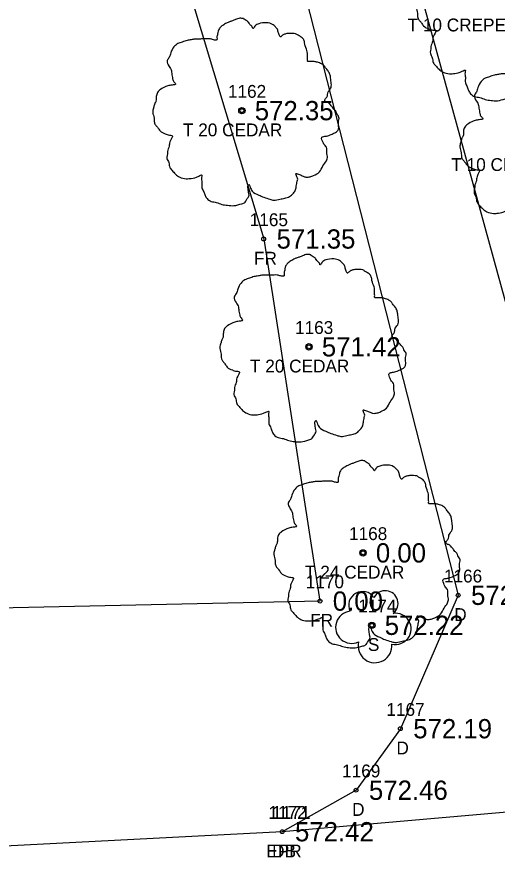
# Model space of a CAD drawing. Extents: x 1529475 to 1532053, y 876698 to 877911.
# Drawn here: x 1531018 to 1531055.4, y 877286.3 to 877352.1 of the extents above; entities that cross this region are included whole.
import ezdxf

# ---------------------------------------------------------------- set-up
doc = ezdxf.new("R2010")
doc.units = 0
for name, color, linetype in [('RD_EX_Driveway', 7, 'Continuous'), ('RD_EX_Driveway_txCode', 7, 'Continuous'), ('RD_EX_Fence_Other', 7, 'Continuous'), ('RD_EX_Fence_Other_txCode', 7, 'Continuous'), ('RD_EX_Road', 7, 'Continuous'), ('RD_EX_Road_txCode', 7, 'Continuous'), ('RD_EX_TX_Driveway_ELEV', 7, 'Continuous'), ('RD_EX_TX_Fence_Other_ELEV', 7, 'Continuous'), ('RD_EX_TX_Road_ELEV', 7, 'Continuous'), ('RD_EX_TX_VEG_ELEV', 7, 'Continuous'), ('RD_EX_VEG', 7, 'Continuous'), ('RD_EX_VEG_txCode', 7, 'Continuous'), ('RD_SMD_Locator', 7, 'Continuous')]:
    doc.layers.add(name, color=color, linetype=linetype)

msp = doc.modelspace()

# ---------------------------------------------------------------- linework, layer by layer
at = {"layer": 'RD_EX_Driveway'}
for points in [[(1531081.114, 877292.384), (1531071.715, 877299.875), (1531056.729, 877327.604), (1531041.174, 877384.235)], [(1531033.235, 877382.278), (1531052.392, 877307.085), (1531047.892, 877296.694), (1531044.444, 877291.901), (1531038.69, 877288.667)]]:
    msp.add_lwpolyline(points, dxfattribs=at)
at = {"layer": 'RD_EX_Fence_Other'}
msp.add_lwpolyline([(1531024.548, 877377.186), (1531037.254, 877334.843), (1531041.631, 877306.635), (1530974.749, 877305.169), (1530894.744, 877304.424), (1530859.113, 877317.256)], dxfattribs=at)
at = {"layer": 'RD_EX_Road'}
msp.add_lwpolyline([(1531606.641, 877133.837), (1531579.15, 877155.048), (1531564.866, 877165.268), (1531535.216, 877186.029), (1531511.532, 877200.27), (1531474.57, 877218.901), (1531430.451, 877239.347), (1531404.48, 877249.379), (1531382.323, 877256.431), (1531333.233, 877270.709), (1531303.666, 877277.444), (1531276.518, 877282.709), (1531237.324, 877287.202), (1531185.802, 877290.94), (1531132.609, 877292.767), (1531081.114, 877292.384), (1531038.69, 877288.667), (1530976.423, 877285.451), (1530941.057, 877284.256)], dxfattribs=at)
at = {"layer": 'RD_EX_VEG'}
for centre, radius in [((1531035.56, 877344.843), 0.25), ((1531035.548, 877344.824), 0.0001), ((1531040.78, 877326.444), 0.25), ((1531040.767, 877326.425), 0.0001), ((1531044.983, 877310.389), 0.25), ((1531044.97, 877310.37), 0.0001), ((1531045.671, 877304.748), 0.25)]:
    msp.add_circle(centre, radius, dxfattribs=at)
for centre, radius, start, end in [((1531044.95, 877306.295), 1.084, 34.97629, 204.75602), ((1531046.716, 877306.45), 0.995, 308.76261, 152.04674), ((1531044.107, 877304.592), 1.257, 96.45179, 294.73401), ((1531047.511, 877304.469), 1.218, 256.56668, 98.10463), ((1531045.917, 877303.152), 1.318, 166.88266, 5.75893)]:
    msp.add_arc(centre, radius, start, end, dxfattribs=at)
for points in [[(1531056.197, 877360.182), (1531055.897, 877360.207), (1531055.572, 877360.107), (1531055.322, 877360.007), (1531055.097, 877359.932), (1531054.872, 877359.832), (1531054.572, 877359.658), (1531054.347, 877359.458), (1531054.222, 877359.208), (1531054.172, 877358.983), (1531054.123, 877358.708), (1531054.123, 877358.533), (1531053.998, 877358.508), (1531053.848, 877358.533), (1531053.598, 877358.608), (1531053.348, 877358.608), (1531053.098, 877358.608), (1531052.748, 877358.583), (1531052.398, 877358.583), (1531052.123, 877358.533), (1531051.799, 877358.483), (1531051.424, 877358.358), (1531051.074, 877358.233), (1531050.774, 877357.983), (1531050.524, 877357.509), (1531050.399, 877357.159), (1531050.249, 877356.909), (1531050.399, 877356.459), (1531050.574, 877356.109), (1531050.599, 877355.909), (1531050.674, 877355.484), (1531050.774, 877355.26), (1531050.899, 877355.06), (1531050.824, 877355.035), (1531050.449, 877354.985), (1531050.149, 877354.885), (1531049.724, 877354.66), (1531049.5, 877354.435), (1531049.4, 877354.11), (1531049.375, 877353.76), (1531049.275, 877353.56), (1531049.2, 877353.285), (1531049.175, 877353.21), (1531049.125, 877352.886), (1531049.225, 877352.436), (1531049.25, 877352.086), (1531049.375, 877351.861), (1531049.525, 877351.686), (1531049.699, 877351.436), (1531050.099, 877351.211), (1531050.424, 877351.111), (1531050.624, 877351.086), (1531050.449, 877350.587), (1531050.399, 877350.237), (1531050.274, 877349.837), (1531050.274, 877349.762), (1531050.224, 877349.287), (1531050.374, 877348.962), (1531050.449, 877348.587), (1531050.624, 877348.363), (1531050.899, 877348.063), (1531051.224, 877347.838), (1531051.724, 877347.713), (1531052.123, 877347.738), (1531052.698, 877347.913), (1531052.948, 877347.988), (1531052.923, 877347.813), (1531052.948, 877347.438), (1531052.948, 877347.013), (1531053.098, 877346.688), (1531053.198, 877346.413), (1531053.348, 877346.163), (1531053.673, 877345.939), (1531054.073, 877345.864), (1531054.497, 877345.714), (1531054.947, 877345.639), (1531055.447, 877345.614), (1531056.047, 877345.764), (1531056.322, 877345.889), (1531056.422, 877346.064), (1531056.621, 877346.438), (1531056.571, 877346.663), (1531056.596, 877347.263), (1531056.696, 877347.088), (1531056.871, 877346.738), (1531057.371, 877346.438), (1531057.771, 877346.263), (1531058.246, 877346.113), (1531058.546, 877346.039), (1531059.02, 877346.113), (1531059.395, 877346.188), (1531059.77, 877346.313), (1531060.07, 877346.588), (1531060.245, 877346.863), (1531060.295, 877347.138), (1531060.37, 877347.513), (1531060.42, 877347.688)], [(1531035.692, 877352.01), (1531035.392, 877352.035), (1531035.067, 877351.935), (1531034.817, 877351.835), (1531034.593, 877351.76), (1531034.368, 877351.66), (1531034.068, 877351.486), (1531033.843, 877351.286), (1531033.718, 877351.036), (1531033.668, 877350.811), (1531033.618, 877350.536), (1531033.618, 877350.361), (1531033.493, 877350.336), (1531033.343, 877350.361), (1531033.093, 877350.436), (1531032.843, 877350.436), (1531032.593, 877350.436), (1531032.244, 877350.411), (1531031.894, 877350.411), (1531031.619, 877350.361), (1531031.294, 877350.311), (1531030.919, 877350.186), (1531030.569, 877350.061), (1531030.269, 877349.811), (1531030.02, 877349.336), (1531029.895, 877348.987), (1531029.745, 877348.737), (1531029.895, 877348.287), (1531030.07, 877347.937), (1531030.094, 877347.737), (1531030.169, 877347.312), (1531030.269, 877347.087), (1531030.394, 877346.887), (1531030.319, 877346.863), (1531029.945, 877346.813), (1531029.645, 877346.713), (1531029.22, 877346.488), (1531028.995, 877346.263), (1531028.895, 877345.938), (1531028.87, 877345.588), (1531028.77, 877345.388), (1531028.695, 877345.113), (1531028.67, 877345.038), (1531028.62, 877344.713), (1531028.72, 877344.264), (1531028.745, 877343.914), (1531028.87, 877343.689), (1531029.02, 877343.514), (1531029.195, 877343.264), (1531029.595, 877343.039), (1531029.92, 877342.939), (1531030.119, 877342.914), (1531029.945, 877342.414), (1531029.895, 877342.065), (1531029.77, 877341.665), (1531029.77, 877341.59), (1531029.72, 877341.115), (1531029.87, 877340.79), (1531029.945, 877340.415), (1531030.119, 877340.19), (1531030.394, 877339.891), (1531030.719, 877339.666), (1531031.219, 877339.541), (1531031.619, 877339.566), (1531032.194, 877339.741), (1531032.443, 877339.816), (1531032.418, 877339.641), (1531032.443, 877339.266), (1531032.443, 877338.841), (1531032.593, 877338.516), (1531032.693, 877338.241), (1531032.843, 877337.991), (1531033.168, 877337.767), (1531033.568, 877337.692), (1531033.993, 877337.542), (1531034.443, 877337.467), (1531034.942, 877337.442), (1531035.542, 877337.592), (1531035.817, 877337.717), (1531035.917, 877337.891), (1531036.117, 877338.266), (1531036.067, 877338.491), (1531036.092, 877339.091), (1531036.192, 877338.916), (1531036.367, 877338.566), (1531036.867, 877338.266), (1531037.266, 877338.091), (1531037.741, 877337.941), (1531038.041, 877337.866), (1531038.516, 877337.941), (1531038.891, 877338.016), (1531039.265, 877338.141), (1531039.565, 877338.416), (1531039.74, 877338.691), (1531039.79, 877338.966), (1531039.865, 877339.341), (1531039.915, 877339.516)], [(1531039.915, 877339.516), (1531039.84, 877339.691), (1531039.79, 877339.941), (1531039.865, 877339.916), (1531040.04, 877339.866), (1531040.315, 877339.741), (1531040.54, 877339.666), (1531040.865, 877339.691), (1531041.14, 877339.791), (1531041.589, 877340.066), (1531041.864, 877340.54), (1531042.139, 877340.94), (1531042.214, 877341.265), (1531042.164, 877341.49), (1531042.139, 877341.99), (1531041.939, 877342.24), (1531041.889, 877342.364), (1531041.789, 877342.764), (1531041.864, 877342.814), (1531042.139, 877342.864), (1531042.514, 877342.989), (1531042.789, 877343.114), (1531043.014, 877343.289), (1531043.089, 877343.514), (1531043.064, 877343.914), (1531043.114, 877344.314), (1531043.039, 877344.464), (1531042.939, 877344.613), (1531042.864, 877344.813), (1531042.714, 877344.963), (1531042.614, 877345.113), (1531042.514, 877345.213), (1531042.389, 877345.363), (1531042.214, 877345.488), (1531042.064, 877345.538), (1531042.014, 877345.688), (1531042.164, 877345.888), (1531042.214, 877345.988), (1531042.239, 877346.213), (1531042.464, 877346.563), (1531042.514, 877346.962), (1531042.464, 877347.387), (1531042.414, 877347.662), (1531042.264, 877347.937), (1531042.064, 877348.187), (1531041.939, 877348.362), (1531041.764, 877348.487), (1531041.44, 877348.612), (1531041.19, 877348.662), (1531040.84, 877348.662), (1531040.64, 877348.712), (1531040.665, 877348.762), (1531040.665, 877348.912), (1531040.665, 877349.187), (1531040.59, 877349.636), (1531040.44, 877350.136), (1531040.44, 877350.161), (1531040.34, 877350.411), (1531040.115, 877350.611), (1531039.94, 877350.711), (1531039.74, 877350.836), (1531039.49, 877350.861), (1531039.191, 877350.861), (1531038.916, 877350.811), (1531038.716, 877350.711), (1531038.541, 877350.586), (1531038.466, 877350.736), (1531038.366, 877351.036), (1531038.316, 877351.186), (1531038.166, 877351.361), (1531037.941, 877351.56), (1531037.491, 877351.685), (1531036.867, 877351.61), (1531036.567, 877351.411), (1531036.417, 877351.236), (1531036.367, 877351.361), (1531036.167, 877351.56), (1531036.067, 877351.735), (1531035.892, 877351.86), (1531035.742, 877351.96), (1531035.642, 877352.01)], [(1531059.602, 877349.308), (1531059.302, 877349.333), (1531058.977, 877349.233), (1531058.728, 877349.133), (1531058.503, 877349.058), (1531058.278, 877348.958), (1531057.978, 877348.783), (1531057.753, 877348.583), (1531057.628, 877348.333), (1531057.578, 877348.108), (1531057.528, 877347.834), (1531057.528, 877347.659), (1531057.403, 877347.634), (1531057.253, 877347.659), (1531057.003, 877347.734), (1531056.753, 877347.734), (1531056.503, 877347.734), (1531056.154, 877347.709), (1531055.804, 877347.709), (1531055.529, 877347.659), (1531055.204, 877347.609), (1531054.829, 877347.484), (1531054.479, 877347.359), (1531054.18, 877347.109), (1531053.93, 877346.634), (1531053.805, 877346.284), (1531053.655, 877346.034), (1531053.805, 877345.585), (1531053.98, 877345.235), (1531054.005, 877345.035), (1531054.08, 877344.61), (1531054.18, 877344.385), (1531054.304, 877344.185), (1531054.23, 877344.16), (1531053.855, 877344.11), (1531053.555, 877344.01), (1531053.13, 877343.785), (1531052.905, 877343.56), (1531052.805, 877343.236), (1531052.78, 877342.886), (1531052.68, 877342.686), (1531052.605, 877342.411), (1531052.58, 877342.336), (1531052.53, 877342.011), (1531052.63, 877341.561), (1531052.655, 877341.211), (1531052.78, 877340.987), (1531052.93, 877340.812), (1531053.105, 877340.562), (1531053.505, 877340.337), (1531053.83, 877340.237), (1531054.03, 877340.212), (1531053.855, 877339.712), (1531053.805, 877339.362), (1531053.68, 877338.962), (1531053.68, 877338.888), (1531053.63, 877338.413), (1531053.78, 877338.088), (1531053.855, 877337.713), (1531054.03, 877337.488), (1531054.304, 877337.188), (1531054.629, 877336.963), (1531055.129, 877336.838), (1531055.529, 877336.863), (1531056.104, 877337.038), (1531056.354, 877337.113), (1531056.329, 877336.938), (1531056.354, 877336.563), (1531056.354, 877336.139), (1531056.503, 877335.814), (1531056.603, 877335.539), (1531056.753, 877335.289), (1531057.078, 877335.064), (1531057.478, 877334.989), (1531057.903, 877334.839), (1531058.353, 877334.764), (1531058.852, 877334.739), (1531059.452, 877334.889), (1531059.727, 877335.014), (1531059.827, 877335.189), (1531060.027, 877335.564), (1531059.977, 877335.789), (1531060.002, 877336.389), (1531060.102, 877336.214), (1531060.277, 877335.864), (1531060.777, 877335.564), (1531061.176, 877335.389), (1531061.651, 877335.239), (1531061.951, 877335.164), (1531062.426, 877335.239), (1531062.801, 877335.314), (1531063.176, 877335.439), (1531063.475, 877335.714), (1531063.65, 877335.989), (1531063.7, 877336.264), (1531063.775, 877336.638), (1531063.825, 877336.813)], [(1531040.911, 877333.611), (1531040.612, 877333.636), (1531040.287, 877333.536), (1531040.037, 877333.436), (1531039.812, 877333.361), (1531039.587, 877333.261), (1531039.287, 877333.086), (1531039.062, 877332.886), (1531038.937, 877332.636), (1531038.887, 877332.412), (1531038.837, 877332.137), (1531038.837, 877331.962), (1531038.712, 877331.937), (1531038.562, 877331.962), (1531038.313, 877332.037), (1531038.063, 877332.037), (1531037.813, 877332.037), (1531037.463, 877332.012), (1531037.113, 877332.012), (1531036.838, 877331.962), (1531036.513, 877331.912), (1531036.139, 877331.787), (1531035.789, 877331.662), (1531035.489, 877331.412), (1531035.239, 877330.937), (1531035.114, 877330.587), (1531034.964, 877330.337), (1531035.114, 877329.888), (1531035.289, 877329.538), (1531035.314, 877329.338), (1531035.389, 877328.913), (1531035.489, 877328.688), (1531035.614, 877328.488), (1531035.539, 877328.463), (1531035.164, 877328.413), (1531034.864, 877328.313), (1531034.439, 877328.088), (1531034.214, 877327.864), (1531034.114, 877327.539), (1531034.089, 877327.189), (1531033.99, 877326.989), (1531033.915, 877326.714), (1531033.89, 877326.639), (1531033.84, 877326.314), (1531033.94, 877325.864), (1531033.965, 877325.515), (1531034.089, 877325.29), (1531034.239, 877325.115), (1531034.414, 877324.865), (1531034.814, 877324.64), (1531035.139, 877324.54), (1531035.339, 877324.515), (1531035.164, 877324.015), (1531035.114, 877323.665), (1531034.989, 877323.266), (1531034.989, 877323.191), (1531034.939, 877322.716), (1531035.089, 877322.391), (1531035.164, 877322.016), (1531035.339, 877321.791), (1531035.614, 877321.491), (1531035.939, 877321.266), (1531036.438, 877321.141), (1531036.838, 877321.166), (1531037.413, 877321.341), (1531037.663, 877321.416), (1531037.638, 877321.241), (1531037.663, 877320.867), (1531037.663, 877320.442), (1531037.813, 877320.117), (1531037.913, 877319.842), (1531038.063, 877319.592), (1531038.388, 877319.367), (1531038.787, 877319.292), (1531039.212, 877319.142), (1531039.662, 877319.067), (1531040.162, 877319.042), (1531040.762, 877319.192), (1531041.036, 877319.317), (1531041.136, 877319.492), (1531041.336, 877319.867), (1531041.286, 877320.092), (1531041.311, 877320.692), (1531041.411, 877320.517), (1531041.586, 877320.167), (1531042.086, 877319.867), (1531042.486, 877319.692), (1531042.961, 877319.542), (1531043.26, 877319.467), (1531043.735, 877319.542), (1531044.11, 877319.617), (1531044.485, 877319.742), (1531044.785, 877320.017), (1531044.96, 877320.292), (1531045.01, 877320.567), (1531045.085, 877320.942), (1531045.135, 877321.116)], [(1531045.135, 877321.116), (1531045.06, 877321.291), (1531045.01, 877321.541), (1531045.085, 877321.516), (1531045.26, 877321.466), (1531045.534, 877321.341), (1531045.759, 877321.266), (1531046.084, 877321.291), (1531046.359, 877321.391), (1531046.809, 877321.666), (1531047.084, 877322.141), (1531047.359, 877322.541), (1531047.434, 877322.866), (1531047.384, 877323.091), (1531047.359, 877323.59), (1531047.159, 877323.84), (1531047.109, 877323.965), (1531047.009, 877324.365), (1531047.084, 877324.415), (1531047.359, 877324.465), (1531047.733, 877324.59), (1531048.008, 877324.715), (1531048.233, 877324.89), (1531048.308, 877325.115), (1531048.283, 877325.515), (1531048.333, 877325.914), (1531048.258, 877326.064), (1531048.158, 877326.214), (1531048.083, 877326.414), (1531047.933, 877326.564), (1531047.833, 877326.714), (1531047.733, 877326.814), (1531047.609, 877326.964), (1531047.434, 877327.089), (1531047.284, 877327.139), (1531047.234, 877327.289), (1531047.384, 877327.489), (1531047.434, 877327.589), (1531047.459, 877327.814), (1531047.684, 877328.163), (1531047.733, 877328.563), (1531047.684, 877328.988), (1531047.634, 877329.263), (1531047.484, 877329.538), (1531047.284, 877329.788), (1531047.159, 877329.963), (1531046.984, 877330.088), (1531046.659, 877330.213), (1531046.409, 877330.262), (1531046.059, 877330.262), (1531045.859, 877330.312), (1531045.884, 877330.362), (1531045.884, 877330.512), (1531045.884, 877330.787), (1531045.809, 877331.237), (1531045.659, 877331.737), (1531045.659, 877331.762), (1531045.559, 877332.012), (1531045.335, 877332.212), (1531045.16, 877332.312), (1531044.96, 877332.437), (1531044.71, 877332.462), (1531044.41, 877332.462), (1531044.135, 877332.412), (1531043.935, 877332.312), (1531043.76, 877332.187), (1531043.685, 877332.337), (1531043.585, 877332.636), (1531043.535, 877332.786), (1531043.385, 877332.961), (1531043.161, 877333.161), (1531042.711, 877333.286), (1531042.086, 877333.211), (1531041.786, 877333.011), (1531041.636, 877332.836), (1531041.586, 877332.961), (1531041.386, 877333.161), (1531041.286, 877333.336), (1531041.111, 877333.461), (1531040.961, 877333.561), (1531040.861, 877333.611)], [(1531045.115, 877317.556), (1531044.815, 877317.581), (1531044.49, 877317.481), (1531044.24, 877317.381), (1531044.015, 877317.306), (1531043.79, 877317.206), (1531043.49, 877317.031), (1531043.266, 877316.831), (1531043.141, 877316.581), (1531043.091, 877316.356), (1531043.041, 877316.082), (1531043.041, 877315.907), (1531042.916, 877315.882), (1531042.766, 877315.907), (1531042.516, 877315.982), (1531042.266, 877315.982), (1531042.016, 877315.982), (1531041.666, 877315.957), (1531041.316, 877315.957), (1531041.042, 877315.907), (1531040.717, 877315.857), (1531040.342, 877315.732), (1531039.992, 877315.607), (1531039.692, 877315.357), (1531039.442, 877314.882), (1531039.317, 877314.532), (1531039.167, 877314.282), (1531039.317, 877313.833), (1531039.492, 877313.483), (1531039.517, 877313.283), (1531039.592, 877312.858), (1531039.692, 877312.633), (1531039.817, 877312.433), (1531039.742, 877312.408), (1531039.367, 877312.358), (1531039.067, 877312.258), (1531038.643, 877312.033), (1531038.418, 877311.808), (1531038.318, 877311.483), (1531038.293, 877311.134), (1531038.193, 877310.934), (1531038.118, 877310.659), (1531038.093, 877310.584), (1531038.043, 877310.259), (1531038.143, 877309.809), (1531038.168, 877309.459), (1531038.293, 877309.234), (1531038.443, 877309.06), (1531038.618, 877308.81), (1531039.017, 877308.585), (1531039.342, 877308.485), (1531039.542, 877308.46), (1531039.367, 877307.96), (1531039.317, 877307.61), (1531039.192, 877307.21), (1531039.192, 877307.135), (1531039.142, 877306.661), (1531039.292, 877306.336), (1531039.367, 877305.961), (1531039.542, 877305.736), (1531039.817, 877305.436), (1531040.142, 877305.211), (1531040.642, 877305.086), (1531041.042, 877305.111), (1531041.616, 877305.286), (1531041.866, 877305.361), (1531041.841, 877305.186), (1531041.866, 877304.811), (1531041.866, 877304.387), (1531042.016, 877304.062), (1531042.116, 877303.787), (1531042.266, 877303.537), (1531042.591, 877303.312), (1531042.991, 877303.237), (1531043.415, 877303.087), (1531043.865, 877303.012), (1531044.365, 877302.987), (1531044.965, 877303.137), (1531045.24, 877303.262), (1531045.34, 877303.437), (1531045.54, 877303.812), (1531045.49, 877304.037), (1531045.515, 877304.637), (1531045.614, 877304.462), (1531045.789, 877304.112), (1531046.289, 877303.812), (1531046.689, 877303.637), (1531047.164, 877303.487), (1531047.464, 877303.412), (1531047.938, 877303.487), (1531048.313, 877303.562), (1531048.688, 877303.687), (1531048.988, 877303.962), (1531049.163, 877304.237), (1531049.213, 877304.512), (1531049.288, 877304.886), (1531049.338, 877305.061)], [(1531049.338, 877305.061), (1531049.263, 877305.236), (1531049.213, 877305.486), (1531049.288, 877305.461), (1531049.463, 877305.411), (1531049.738, 877305.286), (1531049.963, 877305.211), (1531050.287, 877305.236), (1531050.562, 877305.336), (1531051.012, 877305.611), (1531051.287, 877306.086), (1531051.562, 877306.486), (1531051.637, 877306.811), (1531051.587, 877307.035), (1531051.562, 877307.535), (1531051.362, 877307.785), (1531051.312, 877307.91), (1531051.212, 877308.31), (1531051.287, 877308.36), (1531051.562, 877308.41), (1531051.937, 877308.535), (1531052.212, 877308.66), (1531052.437, 877308.835), (1531052.511, 877309.06), (1531052.487, 877309.459), (1531052.536, 877309.859), (1531052.462, 877310.009), (1531052.362, 877310.159), (1531052.287, 877310.359), (1531052.137, 877310.509), (1531052.037, 877310.659), (1531051.937, 877310.759), (1531051.812, 877310.909), (1531051.637, 877311.034), (1531051.487, 877311.084), (1531051.437, 877311.234), (1531051.587, 877311.434), (1531051.637, 877311.533), (1531051.662, 877311.758), (1531051.887, 877312.108), (1531051.937, 877312.508), (1531051.887, 877312.933), (1531051.837, 877313.208), (1531051.687, 877313.483), (1531051.487, 877313.733), (1531051.362, 877313.907), (1531051.187, 877314.032), (1531050.862, 877314.157), (1531050.612, 877314.207), (1531050.262, 877314.207), (1531050.063, 877314.257), (1531050.088, 877314.307), (1531050.088, 877314.457), (1531050.088, 877314.732), (1531050.013, 877315.182), (1531049.863, 877315.682), (1531049.863, 877315.707), (1531049.763, 877315.957), (1531049.538, 877316.156), (1531049.363, 877316.256), (1531049.163, 877316.381), (1531048.913, 877316.406), (1531048.613, 877316.406), (1531048.338, 877316.356), (1531048.138, 877316.256), (1531047.963, 877316.131), (1531047.888, 877316.281), (1531047.789, 877316.581), (1531047.739, 877316.731), (1531047.589, 877316.906), (1531047.364, 877317.106), (1531046.914, 877317.231), (1531046.289, 877317.156), (1531045.989, 877316.956), (1531045.839, 877316.781), (1531045.789, 877316.906), (1531045.589, 877317.106), (1531045.49, 877317.281), (1531045.315, 877317.406), (1531045.165, 877317.506), (1531045.065, 877317.556)]]:
    msp.add_spline(points, degree=3, dxfattribs=at)
at = {"layer": 'RD_SMD_Locator'}
for centre in [(1531035.56, 877344.843), (1531037.254, 877334.843), (1531040.78, 877326.444), (1531044.983, 877310.389), (1531052.392, 877307.085), (1531041.631, 877306.635), (1531045.671, 877304.748), (1531047.892, 877296.694), (1531044.444, 877291.901), (1531038.69, 877288.667), (1531038.69, 877288.667)]:
    msp.add_circle(centre, 0.15, dxfattribs=at)

# ---------------------------------------------------------------- texts
at = {"layer": 'RD_EX_Driveway_txCode'}
for s, p in [('1166', (1531051.282, 877308.085)), ('D', (1531052.085, 877305.085)), ('1167', (1531046.805, 877297.694)), ('D', (1531047.585, 877294.694)), ('1169', (1531043.357, 877292.901)), ('D', (1531044.136, 877289.901)), ('1171', (1531037.911, 877289.667)), ('DB', (1531037.911, 877286.667))]:
    msp.add_text(s, height=1, dxfattribs=at).set_placement(p)
at = {"layer": 'RD_EX_Fence_Other_txCode'}
for s, p in [('1165', (1531036.168, 877335.843)), ('FR', (1531036.498, 877332.843)), ('1170', (1531040.529, 877307.635)), ('FR', (1531040.875, 877304.635))]:
    msp.add_text(s, height=1, dxfattribs=at).set_placement(p)
at = {"layer": 'RD_EX_Road_txCode'}
for s, p in [('1172', (1531037.627, 877289.667)), ('EPR', (1531037.462, 877286.667))]:
    msp.add_text(s, height=1, dxfattribs=at).set_placement(p)
at = {"layer": 'RD_EX_TX_Driveway_ELEV'}
for s, p in [('572.01', (1531053.392, 877306.335)), ('572.19', (1531048.892, 877295.944)), ('572.46', (1531045.444, 877291.151)), ('572.42', (1531039.69, 877287.917))]:
    msp.add_text(s, height=1.5, dxfattribs=at).set_placement(p)
at = {"layer": 'RD_EX_TX_Fence_Other_ELEV'}
for s, p in [('571.35', (1531038.254, 877334.093)), ('0.00', (1531042.631, 877305.885))]:
    msp.add_text(s, height=1.5, dxfattribs=at).set_placement(p)
at = {"layer": 'RD_EX_TX_Road_ELEV'}
msp.add_text('572.42', height=1.5, dxfattribs=at).set_placement((1531039.69, 877287.917))
at = {"layer": 'RD_EX_TX_VEG_ELEV'}
for s, p in [('572.35', (1531036.56, 877344.093)), ('571.42', (1531041.78, 877325.694)), ('0.00', (1531045.983, 877309.639)), ('572.22', (1531046.671, 877303.998))]:
    msp.add_text(s, height=1.5, dxfattribs=at).set_placement(p)
at = {"layer": 'RD_EX_VEG_txCode'}
for s, p in [('T 10 CREPE MYRTLE', (1531048.454, 877351.015)), ('1162', (1531034.473, 877345.843)), ('T 20 CEDAR', (1531030.97, 877342.843)), ('T 10 CREPE MYRTLE', (1531051.86, 877340.141)), ('1163', (1531039.693, 877327.444)), ('T 20 CEDAR', (1531036.189, 877324.444)), ('1168', (1531043.896, 877311.389)), ('T 24 CEDAR', (1531040.471, 877308.389)), ('1174', (1531044.608, 877305.748)), ('S', (1531045.364, 877302.748))]:
    msp.add_text(s, height=1, dxfattribs=at).set_placement(p)

doc.saveas('drawing.dxf')
